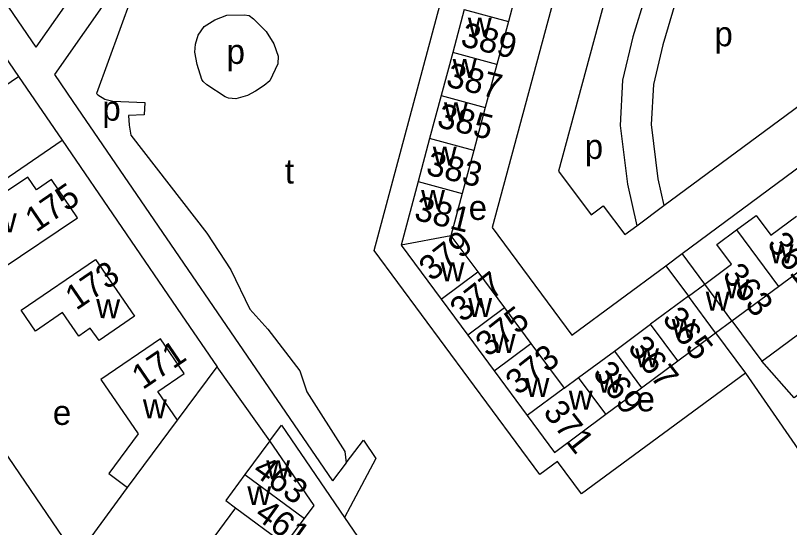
# Model space of a CAD drawing. Extents: x 154320 to 156262, y 382651 to 384180.
# Drawn here: x 155775.5 to 155900.9, y 383331.4 to 383414.4 of the extents above; entities that cross this region are included whole.
import ezdxf

# ---------------------------------------------------------------- set-up
doc = ezdxf.new("R2010")
doc.units = 0
for name, color, linetype in [('BLT_Basislijn', 7, 'Continuous'), ('BLT_Bebouwing', 7, 'Continuous'), ('BLT_Centroide', 7, 'Continuous'), ('BLT_Huisnummer', 7, 'Continuous'), ('BLT_Huisnummer_ tussenligend', 7, 'Continuous'), ('BLT_Onderdoorgang_en_onderverdeling', 7, 'Continuous'), ('BLT_Onderverdeling_panden', 7, 'Continuous')]:
    doc.layers.add(name, color=color, linetype=linetype)

msp = doc.modelspace()

# ---------------------------------------------------------------- linework, layer by layer
at = {"layer": 'BLT_Basislijn'}
for p, q in [((155801.1, 383435.95), (155788.64, 383401.73)), ((155875.44, 383433.65), (155863.47, 383389.12)), ((155880.52, 383383.56), (155928.8, 383419.3)), ((155771.89, 383401.67), (155776.01, 383404.48)), ((155784.83, 383400.43), (155826.84, 383338.97)), ((155753.18, 383373.73), (155783.06, 383394.16)), ((155783.06, 383394.16), (155802.39, 383365.89)), ((155876.14, 383380.31), (155880.52, 383383.56)), ((155874.18, 383378.87), (155876.14, 383380.31)), ((155880.83, 383373.83), (155883.47, 383375.78)), ((155897.76, 383359.4), (155913.86, 383371.37)), ((155802.39, 383365.89), (155808.17, 383357.43)), ((155891.54, 383364.89), (155896.38, 383358.38)), ((155896.38, 383358.38), (155897.76, 383359.4)), ((155801.78, 383348.8), (155808.17, 383357.43)), ((155816.69, 383345.44), (155808.17, 383357.43)), ((155772.5, 383345.46), (155785.39, 383326.61)), ((155829.07, 383341.91), (155826.84, 383338.97)), ((155833.88, 383342.6), (155829.72, 383334.77)), ((155785.39, 383326.61), (155793.67, 383337.88)), ((155829.72, 383334.77), (155828.8, 383333.07))]:
    msp.add_line(p, q, dxfattribs=at)
for points in [[(155724.46, 383488.76), (155778.83, 383409.21)], [(155725.22, 383478.78), (155776.01, 383404.48)], [(155893.74, 383356.42), (155867.19, 383336.88), (155863.3, 383342.14), (155860.43, 383340.02), (155833.63, 383376.29), (155853.7, 383451.27), (155857.69, 383450.39)], [(155864.7, 383448.43), (155870.72, 383446.91), (155852.73, 383380), (155865.63, 383362.58)], [(155783.41, 383447.12), (155795.54, 383429.47), (155791.45, 383418.56), (155781.85, 383404.79)], [(155879.36, 383437.25), (155880.77, 383433.8), (155882.14, 383428.69), (155883, 383420.76), (155882.37, 383416.32), (155880.32, 383409.6), (155878.81, 383403.15), (155878.46, 383396.68), (155879.53, 383387.88), (155880.52, 383383.56)], [(155875.44, 383433.65), (155876.02, 383432.2), (155877.22, 383427.77), (155877.96, 383420.85), (155877.47, 383417.41), (155875.49, 383410.9), (155873.84, 383403.86), (155873.44, 383396.51), (155874.6, 383387.02), (155876.14, 383380.31)], [(155787.63, 383432.15), (155789.95, 383428.78), (155786.99, 383420.9), (155778.83, 383409.21)], [(155883.47, 383375.78), (155937.95, 383416.11), (155942.37, 383410.13)], [(155776.01, 383404.48), (155783.06, 383394.16)], [(155781.85, 383404.79), (155784.83, 383400.43)], [(155788.64, 383401.73), (155788.85, 383401.48), (155790.02, 383400.79), (155791.27, 383400.48), (155796.46, 383400.26), (155796.38, 383398.25), (155793.8, 383398.17), (155793.94, 383396.6), (155794.22, 383394.98), (155806.53, 383379.12), (155810.38, 383373.18), (155813.47, 383366.8), (155816.4, 383363.57), (155821.56, 383356.78), (155822.71, 383353.42), (155828.85, 383343.72), (155829.07, 383341.91)], [(155863.47, 383389.12), (155868.72, 383382.04), (155870.71, 383383.54), (155874.18, 383378.87)], [(155887.13, 383370.84), (155883.47, 383375.78)], [(155865.63, 383362.58), (155880.83, 383373.83)], [(155880.83, 383373.83), (155884.49, 383368.89)], [(155913.86, 383371.37), (155914.95, 383369.91), (155912.12, 383367.27), (155909.43, 383362.99), (155907.81, 383358.83), (155906.51, 383356.62), (155905.42, 383355.36), (155901.62, 383352.44), (155896.38, 383358.38)], [(155888.9, 383362.94), (155893.74, 383356.42)], [(155893.74, 383356.42), (155901.72, 383344.89), (155905.64, 383338.8)], [(155829.07, 383341.91), (155831.87, 383345.58), (155833.88, 383342.6)]]:
    msp.add_lwpolyline(points, dxfattribs=at)
msp.add_lwpolyline([(155804.58, 383408.39), (155804.7, 383409.7), (155805.12, 383411.15), (155806.09, 383412.58), (155807.78, 383413.64), (155809.74, 383414.38), (155812.53, 383414.47), (155813.38, 383414.34), (155814.07, 383413.82), (155816.13, 383411.78), (155817.37, 383409.78), (155818.05, 383407.74), (155818.02, 383406.53), (155816.72, 383403.75), (155815.78, 383403), (155814.4, 383402.09), (155813.12, 383401.41), (155811.21, 383400.86), (155810.01, 383400.98), (155809.47, 383401.2), (155806.52, 383403.11), (155805.89, 383403.67), (155805.69, 383403.98), (155804.92, 383406.4)], close=True, dxfattribs=at)
at = {"layer": 'BLT_Bebouwing'}
for p, q in [((155857.19, 383420.36), (155855.33, 383413.4)), ((155848.18, 383415.32), (155846.32, 383408.35)), ((155855.33, 383413.4), (155853.47, 383406.44)), ((155846.32, 383408.35), (155844.45, 383401.39)), ((155853.47, 383406.44), (155851.6, 383399.47)), ((155844.45, 383401.39), (155842.59, 383394.42)), ((155851.6, 383399.47), (155849.74, 383392.51)), ((155842.59, 383394.42), (155840.72, 383387.46)), ((155849.74, 383392.51), (155847.88, 383385.54)), ((155840.72, 383387.46), (155837.96, 383377.17)), ((155847.88, 383385.54), (155846.04, 383378.68)), ((155846.04, 383378.68), (155850.37, 383372.84)), ((155837.96, 383377.17), (155844.43, 383368.43)), ((155850.37, 383372.84), (155854.7, 383367)), ((155884.49, 383368.89), (155887.13, 383370.84)), ((155891.54, 383364.89), (155899.06, 383370.45)), ((155844.43, 383368.43), (155848.75, 383362.59)), ((155854.7, 383367), (155858.99, 383361.21)), ((155872.5, 383360), (155878.37, 383364.35)), ((155888.9, 383362.94), (155891.54, 383364.89)), ((155882.78, 383358.4), (155888.9, 383362.94)), ((155848.75, 383362.59), (155853.03, 383356.8)), ((155858.99, 383361.21), (155864.36, 383353.97)), ((155866.69, 383355.7), (155872.5, 383360)), ((155876.91, 383354.05), (155882.78, 383358.4)), ((155853.03, 383356.8), (155858.4, 383349.56)), ((155864.36, 383353.97), (155866.69, 383355.7)), ((155871.14, 383349.78), (155876.91, 383354.05)), ((155858.4, 383349.56), (155862.8, 383343.6)), ((155862.8, 383343.6), (155871.14, 383349.78)), ((155811.17, 383334.61), (155806.72, 383328.6)), ((155821.81, 383332.18), (155822.32, 383332.87)), ((155828.8, 383333.07), (155830.92, 383329.99))]:
    msp.add_line(p, q, dxfattribs=at)
for points in [[(155777.52, 383388.19), (155767.61, 383381.54), (155773.21, 383373.26), (155785.57, 383381.57), (155781.34, 383387.77), (155778.94, 383386.11)], [(155776.45, 383366.62), (155788.46, 383374.82), (155794.78, 383365.63), (155789.06, 383361.71), (155787.64, 383363.72), (155785.8, 383362.42), (155783.13, 383366.23), (155778.75, 383363.24)]]:
    msp.add_lwpolyline(points, close=True, dxfattribs=at)
for points in [[(155892.27, 383379.62), (155895.44, 383381.97), (155897.82, 383378.76), (155901.97, 383381.83)], [(155887.13, 383370.84), (155891.48, 383374.06), (155889.1, 383377.28), (155892.27, 383379.62)], [(155899.06, 383370.45), (155903.95, 383374.07), (155907.4, 383369.41), (155910.07, 383371.38), (155906.62, 383376.04)], [(155884.49, 383368.89), (155878.37, 383364.35)], [(155801.78, 383348.8), (155798.59, 383353.47), (155802.84, 383356.38), (155798.99, 383362.01), (155789.34, 383355.42), (155795.39, 383346.62), (155790.62, 383340.15), (155793.67, 383337.88)], [(155793.67, 383337.88), (155801.78, 383348.8)], [(155816.69, 383345.44), (155818.58, 383347.99), (155828.8, 383333.07)], [(155816.69, 383345.44), (155812.68, 383340)], [(155812.68, 383340), (155809.56, 383335.78), (155811.17, 383334.61)]]:
    msp.add_lwpolyline(points, dxfattribs=at)
at = {"layer": 'BLT_Onderdoorgang_en_onderverdeling'}
for points in [[(155891.54, 383364.89), (155887.13, 383370.84)], [(155888.9, 383362.94), (155884.49, 383368.89)]]:
    msp.add_lwpolyline(points, dxfattribs=at)
at = {"layer": 'BLT_Onderverdeling_panden'}
for p, q in [((155848.18, 383415.32), (155855.33, 383413.4)), ((155853.47, 383406.44), (155846.32, 383408.35)), ((155844.45, 383401.39), (155851.6, 383399.47)), ((155849.74, 383392.51), (155842.59, 383394.42)), ((155840.72, 383387.46), (155847.88, 383385.54)), ((155892.27, 383379.62), (155899.06, 383370.45)), ((155846.04, 383378.68), (155837.96, 383377.17)), ((155844.43, 383368.43), (155850.37, 383372.84)), ((155854.7, 383367), (155848.75, 383362.59)), ((155882.78, 383358.4), (155878.37, 383364.35)), ((155853.03, 383356.8), (155858.99, 383361.21)), ((155872.5, 383360), (155876.91, 383354.05)), ((155871.14, 383349.78), (155866.69, 383355.7)), ((155864.36, 383353.97), (155858.4, 383349.56)), ((155812.68, 383340), (155822.32, 383332.87)), ((155811.17, 383334.61), (155819.21, 383328.66)), ((155819.21, 383328.66), (155821.81, 383332.18))]:
    msp.add_line(p, q, dxfattribs=at)
msp.add_lwpolyline([(155822.32, 383332.87), (155823.87, 383334.98), (155816.69, 383345.44)], dxfattribs=at)

# ---------------------------------------------------------------- texts
at = {"layer": 'BLT_Centroide'}
for s, p in [('w', (155848.77, 383410.93)), ('p', (155888.7, 383409.37)), ('p', (155809.71, 383406.51)), ('w', (155846.33, 383404.21)), ('p', (155789.59, 383397.32)), ('w', (155844.91, 383397.21)), ('w', (155843.1, 383390.04)), ('p', (155867.7, 383391.12)), ('t', (155819.15, 383387.13)), ('w', (155841.2, 383383.03)), ('e', (155848.91, 383381.24)), ('w', (155897.64, 383374.23)), ('w', (155844.37, 383371.32)), ('w', (155890.47, 383368.55)), ('w', (155887.3, 383366.54)), ('w', (155848.84, 383365.52)), ('w', (155881.8, 383362.11)), ('w', (155852.64, 383359.68)), ('w', (155875.86, 383357.38)), ('w', (155858.11, 383352.57)), ('w', (155869.82, 383353.24)), ('w', (155865.12, 383350.5)), ('e', (155876.09, 383350.24)), ('w', (155796.16, 383349.1)), ('e', (155781.58, 383348.04)), ('w', (155816.12, 383339.25)), ('w', (155813.06, 383335.05))]:
    msp.add_text(s, height=4, dxfattribs=at).set_placement(p)
for p in [(155771.83, 383379.25), (155788.58, 383365.34)]:
    msp.add_text('w', height=4, rotation=359.5, dxfattribs=at).set_placement(p)
at = {"layer": 'BLT_Huisnummer'}
for s, rotation, p in [('387', 346.0883, (155845.07, 383402.92)), ('383', 346.0883, (155841.82, 383388.64)), ('175', 34.3537, (155778.86, 383379.14)), ('379', 38.0883, (155842.87, 383371.18)), ('173', 34.3547, (155785.36, 383366.5)), ('363', 308.0883, (155889.85, 383372.28)), ('375', 38.0883, (155852.02, 383358.93)), ('365', 308.0883, (155880.12, 383365.21)), ('171', 34.3547, (155796.13, 383353.65)), ('369', 308.0883, (155868.85, 383356.41)), ('371', 308.0883, (155860.83, 383350.08)), ('463', 324.4158, (155813.7, 383340.18))]:
    msp.add_text(s, height=4, rotation=rotation, dxfattribs=at).set_placement(p)
at = {"layer": 'BLT_Huisnummer_ tussenligend'}
for s, rotation, p in [('389', 346.0883, (155847.42, 383409.46)), ('385', 346.0883, (155843.6, 383396.34)), ('381', 346.0883, (155839.91, 383381.32)), ('361', 308.0883, (155897.08, 383377.33)), ('377', 38.0883, (155847.9, 383364.52)), ('367', 308.0883, (155874.53, 383360.5)), ('373', 38.0883, (155856.89, 383352.74)), ('461', 324.4158, (155814.04, 383333.07))]:
    msp.add_text(s, height=4, rotation=rotation, dxfattribs=at).set_placement(p)

doc.saveas('drawing.dxf')
